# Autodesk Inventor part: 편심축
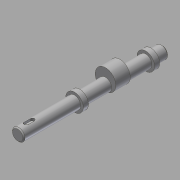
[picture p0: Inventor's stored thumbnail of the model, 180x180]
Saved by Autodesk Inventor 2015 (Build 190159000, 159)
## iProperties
Created: 2016-02
Part Number: 편심축
Material: 강철, 연강
Document SubType Name: Modeling
Designer: mduedu
Density: 1 g/cm^3
Appearance: 강철
Author: mduedu
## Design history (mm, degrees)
sketch "스케치1"
  geometry: C1 r 6 at (0, 0); 1 further point
  constraints: 1 centre point, 1 coincident
  dimensions: "d0" = 12 diameter of C1
extrude "돌출1" new body sketch "스케치1" distance "d1" = 140; taper "d2" = 0 deg
chamfer "모따기1" distance "d3" = 1; stored, may be unused: second distance "d4" = 2, angle "d5" = 45 deg
node "작업 평면1"
sketch "스케치2"
  geometry: C1 r 10 at (0, 4); C2 r 6 at (0, 0) reference; 1 further point
  constraints: 1 centre point, 1 tangent, 1 vertical alignment
  dimensions: "d7" = 20 diameter of C1
extrude "돌출2" join sketch "스케치2" stored distance "d8" = 14; taper "d9" = 0 deg
node "작업 평면2"
sketch "스케치3"
  geometry: C1 r 8.5 at (0, 0); 1 further point
  constraints: 1 centre point, 1 coincident
  dimensions: "d12" = 17 diameter of C1
extrude "돌출3" join sketch "스케치3" distance "d13" = 5; taper "d14" = 0 deg
node "작업 평면3"
sketch "스케치4"
  geometry: L1 (-5, 140)-(5, 140) reference; L2 (0, 140)-(0, 0); L3 (-2, 132)-(-2, 126); L4 (2, 126)-(2, 132); A1 r 2 centre (0, 132) between (2, 132) and (-2, 132); A2 r 2 centre (0, 126) between (-2, 126) and (2, 126)
  constraints: 6 end point, 4 point on circle, 4 tangent, 2 centre point, 2 point on line, 1 midpoint, 1 parallel, 1 perpendicular
  dimensions: "d15" = 4 distance between parallel lines of L3 L4; "d17" = 6 distance edge to line of A1 L1; "d18" = 10 dimension on A2 A1
extrude "돌출4" cut sketch "스케치4" distance "d19" = 2.5; taper "d20" = 0 deg
sketch "스케치5"
  geometry: L1 (6, 55)-(6, 139) reference; L2 (-6, 55)-(-6, 139) reference; L3 (6, 115)-(-6, 115); L4 (-5, 140)-(5, 140) reference; L5 (6, 116.5)-(4.5, 115); L6 (6, 116.5)-(6, 115); L7 (4.5, 115)-(6, 115); 1 further point
  constraints: 8 end point, 4 point on line, 2 collinear, 1 perpendicular
  dimensions: "d21" = 25 distance between parallel lines of L3 L4; "d22" = 3 diameter of L5.start L3; "d24" = 45 deg angle of L3 L5
revolve "회전1" sketch "스케치5" stored, may be unused: angle "d25" = 90 deg
sketch "스케치6"
  geometry: L1 (6, 116.5)-(4.5, 115) reference; L2 (6, 113.5)-(4.5, 115) reference; 2 further points
  constraints: 1 coincident
node "작업 평면4"
sketch "스케치7"
  geometry: C1 r 8.5 at (0, -4); 1 further point
  constraints: 1 centre point, 1 coincident
  dimensions: "d27" = 17 diameter of C1
extrude "돌출5" join sketch "스케치7" distance "d29" = 5; taper "d30" = 0 deg
node "솔리드1"
other parameters: "d6" = -48, "d11" = -11
